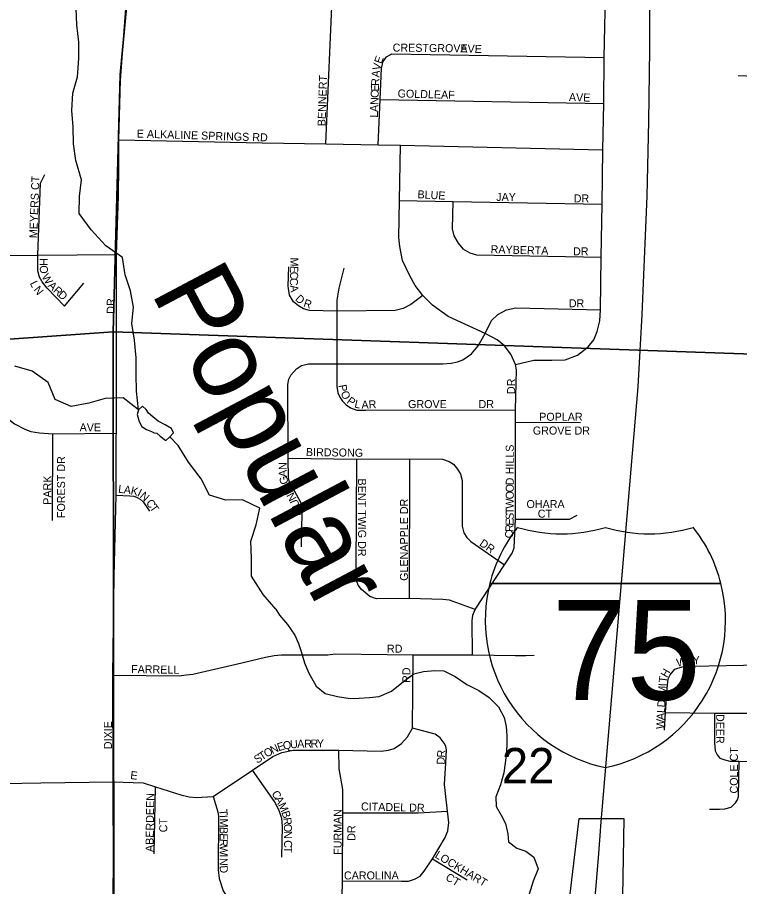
# Model space of a CAD drawing. Extents: x 8.5 to 81.5, y -1.2 to 22.4.
# Drawn here: x 52.1 to 52.954, y 18.242 to 19.27 of the extents above; entities that cross this region are included whole.
import ezdxf

# ---------------------------------------------------------------- set-up
doc = ezdxf.new("R2010")
doc.units = 0
for name, color, linetype in [('GM_X_City_Street', 7, 'Continuous'), ('GM_X_City_Street_Text', 7, 'Continuous'), ('GM_X_Corporation', 7, 'Continuous'), ('GM_X_Interstate_Route', 7, 'Continuous'), ('GM_X_Interstate_Shield', 7, 'Continuous'), ('GM_X_Minor_Lake', 7, 'Continuous'), ('GM_X_Minor_River', 7, 'Continuous'), ('GM_X_Minor_River_Text', 7, 'Continuous'), ('GM_X_Section', 7, 'Continuous'), ('GM_X_Section_Text', 7, 'Continuous')]:
    doc.layers.add(name, color=color, linetype=linetype)

msp = doc.modelspace()

# ---------------------------------------------------------------- linework, layer by layer
at = {"layer": 'GM_X_City_Street'}
for points in [[(52.2203, 19.0942), (52.2204, 19.1255), (52.2222, 19.196), (52.2289, 19.2859), (52.2345, 19.3364), (52.248, 19.4726), (52.2538, 19.5299), (52.2571, 19.5612)], [(52.4651, 19.1207), (52.4735, 19.3103), (52.4794, 19.4085)], [(52.6891, 18.8597), (52.711, 18.8647), (52.7324, 18.8647), (52.7481, 18.8653), (52.7627, 18.8707), (52.7753, 18.8807), (52.7818, 18.8889), (52.7858, 18.8985), (52.789, 18.9113), (52.7899, 18.9244), (52.7905, 18.9867), (52.7919, 19.0492), (52.7927, 19.1136), (52.7937, 19.1683), (52.7942, 19.2229), (52.7953, 19.2774), (52.795, 19.2908), (52.7938, 19.2992), (52.7896, 19.3089), (52.7833, 19.3181), (52.7659, 19.3363), (52.7597, 19.3471), (52.7567, 19.3597), (52.7551, 19.3906)], [(52.5268, 19.1196), (52.5291, 19.1731), (52.5308, 19.2103), (52.5328, 19.2181), (52.5368, 19.2234), (52.5431, 19.2273)], [(52.5431, 19.2273), (52.7942, 19.2229)], [(52.9524, 19.2013), (53.238, 19.1895)], [(52.5291, 19.1731), (52.7937, 19.1683)], [(52.2204, 19.1255), (52.3897, 19.1217), (52.4651, 19.1207), (52.5268, 19.1196), (52.5534, 19.1192), (52.7927, 19.1136)], [(52.6385, 18.5162), (52.6382, 18.5563), (52.639, 18.5631), (52.6416, 18.5697), (52.6764, 18.6228), (52.6854, 18.6366), (52.6876, 18.643), (52.6891, 18.6768), (52.6891, 18.7915), (52.6893, 18.8059), (52.6906, 18.8533), (52.6891, 18.8597), (52.6837, 18.8718), (52.6763, 18.8816), (52.6677, 18.889), (52.6533, 18.8962), (52.6098, 18.9164), (52.5911, 18.9297), (52.5797, 18.9413), (52.5706, 18.9532), (52.5643, 18.9646), (52.5558, 18.9828), (52.5527, 18.9991), (52.5513, 19.0099), (52.5521, 19.0538), (52.5534, 19.1192)], [(52.2173, 18.7751), (52.2174, 18.7786), (52.2176, 18.9899), (52.2201, 19.0589), (52.2203, 19.0942)], [(52.1246, 18.9891), (52.1278, 19.0743), (52.1327, 19.0845)], [(52.5521, 19.0538), (52.6152, 19.0525), (52.7919, 19.0492)], [(52.6152, 19.0525), (52.6144, 19.0201), (52.6164, 19.0118), (52.6215, 19.0031), (52.627, 18.9963), (52.6353, 18.9917), (52.6431, 18.9894), (52.7905, 18.9867)], [(51.7191, 18.9313), (51.9795, 18.9475), (51.9902, 18.9492), (52.047, 18.979), (52.0616, 18.9857), (52.0679, 18.9879), (52.0756, 18.9884), (52.1246, 18.9891), (52.2176, 18.9899)], [(52.1563, 18.9285), (52.1356, 18.9499), (52.1296, 18.9574), (52.1264, 18.9628), (52.1247, 18.9703), (52.1246, 18.9891)], [(52.5797, 18.9413), (52.5654, 18.9307), (52.5563, 18.926), (52.5472, 18.9235), (52.4781, 18.9228), (52.4458, 18.9235), (52.4387, 18.9256), (52.4329, 18.9289), (52.427, 18.9336), (52.4223, 18.9417), (52.4207, 18.9523), (52.4214, 18.9752)], [(52.4863, 18.9735), (52.4804, 18.9499), (52.4781, 18.9356), (52.4781, 18.9228), (52.478, 18.8605), (52.4781, 18.8336), (52.4794, 18.8262), (52.4818, 18.821), (52.4847, 18.8164), (52.4889, 18.8118), (52.4944, 18.8084), (52.5018, 18.8057), (52.5118, 18.8058), (52.6893, 18.8059)], [(52.1563, 18.9285), (52.1789, 18.9557)], [(52.4364, 18.644), (52.437, 18.6847), (52.437, 18.6911), (52.4357, 18.6963), (52.4283, 18.7096), (52.423, 18.7178), (52.4208, 18.7248), (52.4205, 18.7487), (52.42, 18.8359), (52.4213, 18.8425), (52.4235, 18.847), (52.4303, 18.8544), (52.4364, 18.8585), (52.4445, 18.8605), (52.478, 18.8605), (52.6033, 18.8605), (52.6132, 18.8611), (52.6206, 18.8627), (52.6271, 18.8653), (52.6373, 18.8723), (52.6452, 18.8816), (52.6533, 18.8962), (52.661, 18.9116), (52.6685, 18.9189), (52.6787, 18.9244), (52.6896, 18.9265), (52.7899, 18.9244)], [(51.7609, 18.7739), (51.799, 18.7725), (51.8074, 18.773), (51.8146, 18.7746), (51.8486, 18.7875), (51.8997, 18.8069), (51.9083, 18.8096), (51.9153, 18.8107), (52.0531, 18.8123), (52.0634, 18.8118), (52.072, 18.8085), (52.0969, 18.7893), (52.1092, 18.7833), (52.1164, 18.7805), (52.1264, 18.779), (52.1424, 18.7778), (52.2174, 18.7786)], [(52.6891, 18.7915), (52.766, 18.791)], [(52.1418, 18.6753), (52.1424, 18.7778)], [(52.2138, 18.3662), (52.2133, 18.4923), (52.2149, 18.6092), (52.2171, 18.7052), (52.2173, 18.7751)], [(52.4205, 18.7487), (52.5016, 18.7477), (52.5643, 18.748), (52.6028, 18.7477), (52.6109, 18.745), (52.6159, 18.7417), (52.6209, 18.736), (52.6243, 18.7299), (52.6262, 18.7226), (52.6261, 18.6686), (52.6283, 18.6606), (52.6318, 18.6549), (52.6366, 18.6501), (52.6764, 18.6228)], [(52.6416, 18.5697), (52.6114, 18.581), (52.6033, 18.5816), (52.5639, 18.5829), (52.5251, 18.5823), (52.5172, 18.5853), (52.5072, 18.5936), (52.5034, 18.5987), (52.5019, 18.603), (52.5012, 18.6096), (52.5011, 18.6176), (52.5016, 18.7477)], [(52.5639, 18.5829), (52.5643, 18.748)], [(52.2171, 18.7052), (52.2332, 18.7044), (52.2379, 18.7038), (52.2412, 18.7028), (52.2455, 18.7005), (52.2492, 18.6971), (52.2565, 18.6861)], [(52.6891, 18.6768), (52.7533, 18.6769), (52.762, 18.6816)], [(52.8656, 18.427), (52.8665, 18.4479), (52.8686, 18.4769), (52.8697, 18.4878), (52.8721, 18.4926), (52.8777, 18.4992), (52.8865, 18.5021), (52.8975, 18.5028), (53.0204, 18.5053), (53.0789, 18.5046), (53.0959, 18.504), (53.1052, 18.5047), (53.1139, 18.5089), (53.126, 18.5178), (53.1646, 18.5444), (53.1712, 18.5485), (53.1779, 18.5495), (53.2316, 18.5496)], [(52.2133, 18.4923), (52.2918, 18.4916), (52.3, 18.4924), (52.3079, 18.4935), (52.359, 18.5052), (52.3936, 18.5134), (52.4039, 18.5155), (52.4126, 18.5161), (52.4673, 18.5162), (52.4762, 18.5175), (52.5683, 18.5163), (52.6385, 18.5162), (52.689, 18.5154), (52.7013, 18.5155), (52.7114, 18.5157)], [(52.2138, 18.3662), (52.2492, 18.3649), (52.2636, 18.3601), (52.2938, 18.3507), (52.3033, 18.3482), (52.3118, 18.3474), (52.332, 18.3486), (52.3785, 18.3799), (52.4023, 18.3958), (52.4129, 18.4009), (52.4264, 18.4034), (52.4803, 18.4035), (52.5303, 18.4025), (52.539, 18.4033), (52.5457, 18.4054), (52.5544, 18.4112), (52.5616, 18.4192), (52.5675, 18.4296), (52.5683, 18.5163)], [(52.8665, 18.4479), (52.9246, 18.4471), (53.0761, 18.4473)], [(52.9246, 18.4471), (52.9244, 18.4127), (52.9254, 18.4027), (52.9275, 18.398), (52.9309, 18.3942), (52.9368, 18.3921), (52.9425, 18.3904), (52.9537, 18.3903), (53.022, 18.3893), (53.0309, 18.3896), (53.0373, 18.3907), (53.0463, 18.3938), (53.0537, 18.3975), (53.0607, 18.3997), (53.0893, 18.4003)], [(52.4847, 18.2489), (52.5547, 18.2484), (52.5629, 18.2487), (52.5697, 18.2511), (52.5766, 18.2546), (52.5812, 18.2603), (52.5912, 18.275), (52.6061, 18.3001), (52.6093, 18.308), (52.6104, 18.318), (52.6089, 18.3315), (52.6066, 18.3523), (52.6054, 18.363), (52.607, 18.3884), (52.6077, 18.4038), (52.6071, 18.4082), (52.605, 18.4119), (52.6004, 18.418), (52.5943, 18.4223), (52.5675, 18.4296)], [(52.4832, 18.1724), (52.4847, 18.2489), (52.4852, 18.3294), (52.4852, 18.3569), (52.4807, 18.3814), (52.4803, 18.4035)], [(52.9188, 18.3337), (52.9304, 18.3337), (52.9366, 18.334), (52.9444, 18.3362), (52.9495, 18.3413), (52.9517, 18.3448), (52.9529, 18.3486), (52.9537, 18.3903)], [(52.4132, 18.277), (52.414, 18.3134), (52.4129, 18.3226), (52.4098, 18.3321), (52.4042, 18.3426), (52.3785, 18.3799)], [(51.7078, 18.3589), (51.7122, 18.359), (51.8946, 18.3605), (52.0166, 18.3628), (52.0609, 18.3636), (52.1282, 18.3647), (52.2138, 18.3662)], [(52.2123, 18.0013), (52.2118, 18.0943), (52.212, 18.1616), (52.214, 18.2623), (52.2138, 18.3662)], [(52.2622, 18.281), (52.2636, 18.3601)], [(52.332, 18.3486), (52.3373, 18.3307), (52.3382, 18.3251), (52.3376, 18.2621), (52.3388, 18.2515), (52.3438, 18.2372), (52.3494, 18.2285), (52.3558, 18.2206), (52.3616, 18.2159), (52.4379, 18.1824), (52.4513, 18.1763), (52.4635, 18.173), (52.4832, 18.1724), (52.5694, 18.1717), (52.6621, 18.172), (52.6715, 18.1696), (52.6774, 18.1655), (52.6857, 18.1561)], [(52.4852, 18.3294), (52.5743, 18.3292), (52.6089, 18.3315)], [(52.5912, 18.275), (52.632, 18.2503)]]:
    msp.add_lwpolyline(points, dxfattribs=at)
at = {"layer": 'GM_X_Corporation'}
msp.add_lwpolyline([(52.7421, 18.1344), (52.7644, 18.3228), (52.8174, 18.3227), (52.8146, 18.1614)], dxfattribs=at)
at = {"layer": 'GM_X_Interstate_Route'}
for points in [[(52.7898, 18.3076), (52.7903, 18.3139), (52.8344, 18.8332), (52.839, 18.9187), (52.8449, 19.0588), (52.8469, 19.1476), (52.8482, 19.2324), (52.8482, 19.3199), (52.8469, 19.4954), (52.8469, 19.5737), (52.8476, 19.7116), (52.8462, 19.8917), (52.8462, 19.9189), (52.8456, 20.1807), (52.8462, 20.2622), (52.8469, 20.3644), (52.8456, 20.4852), (52.846, 20.5233), (52.8459, 20.8515)], [(52.7548, 17.8881), (52.7556, 17.8973), (52.7613, 17.9651), (52.7626, 17.9775), (52.7635, 17.9886), (52.7656, 18.0162), (52.7663, 18.0252), (52.7683, 18.0482), (52.7793, 18.1944), (52.7842, 18.2384), (52.7876, 18.2811), (52.7898, 18.3076)]]:
    msp.add_lwpolyline(points, dxfattribs=at)
at = {"layer": 'GM_X_Interstate_Shield'}
for p, q in [((52.6589, 18.6005), (52.9322, 18.6005)), ((52.9322, 18.6005), (52.6589, 18.6005)), ((52.9322, 18.6005), (52.6589, 18.6005))]:
    msp.add_line(p, q, dxfattribs=at)
for centre, start, end in [((52.8311, 18.557), 141.669, 165.8066), ((52.7437, 18.8369), 253.0091, 286.9909), ((52.8474, 18.8369), 253.0091, 286.9909), ((52.76, 18.557), 14.1934, 38.331), ((52.8311, 18.557), 165.8066, 258.463), ((52.76, 18.557), 281.537, 14.1934)]:
    msp.add_arc(centre, 0.1776, start, end, dxfattribs=at)
at = {"layer": 'GM_X_Minor_Lake'}
for points in [[(52.2808, 18.7739), (52.2851, 18.7788), (52.2825, 18.7838), (52.275, 18.7881), (52.2667, 18.7928), (52.2607, 18.7978), (52.2554, 18.8021), (52.2525, 18.8063), (52.2484, 18.8102), (52.2434, 18.8061), (52.2421, 18.8004), (52.2443, 18.7924), (52.2476, 18.7863), (52.2532, 18.7827), (52.2589, 18.7804), (52.2623, 18.7788)], [(52.2623, 18.7788), (52.2653, 18.7784), (52.2691, 18.7749), (52.2758, 18.7698), (52.2808, 18.7739)]]:
    msp.add_lwpolyline(points, dxfattribs=at)
at = {"layer": 'GM_X_Minor_River'}
for points in [[(52.2434, 18.8061), (52.2413, 18.8283), (52.2409, 18.848), (52.2409, 18.8674), (52.239, 18.8883), (52.2359, 18.9081), (52.2375, 18.9274), (52.234, 18.9468), (52.228, 18.9658), (52.2245, 18.9863), (52.2051, 19), (52.1876, 19.019), (52.1736, 19.0384), (52.1739, 19.0585), (52.1762, 19.0782), (52.1694, 19.101), (52.1667, 19.1208), (52.1663, 19.1409), (52.1648, 19.1599), (52.1659, 19.1804), (52.1713, 19.1998), (52.1732, 19.2215), (52.1732, 19.2408), (52.1705, 19.2613), (52.1701, 19.2807)], [(52.2434, 18.8061), (52.2253, 18.8203), (52.204, 18.8196), (52.185, 18.8139), (52.1641, 18.8101), (52.1451, 18.8184), (52.1367, 18.8382), (52.1177, 18.8519), (52.0975, 18.8576)], [(52.4058, 18.5703), (52.3911, 18.5878), (52.3771, 18.6092), (52.3771, 18.6307), (52.3763, 18.6505), (52.3828, 18.6702), (52.3869, 18.6896), (52.3664, 18.6995), (52.347, 18.6991), (52.3276, 18.7052), (52.3177, 18.7246), (52.3029, 18.7443), (52.2903, 18.7637), (52.2808, 18.7739)], [(52.4058, 18.5703), (52.4101, 18.5632), (52.4198, 18.552), (52.4283, 18.5397), (52.4326, 18.5297), (52.4359, 18.5201), (52.4398, 18.5067), (52.4445, 18.4953), (52.4537, 18.4791), (52.4641, 18.4705), (52.4789, 18.4668), (52.494, 18.4646), (52.5043, 18.4651), (52.5168, 18.4656), (52.5283, 18.4669), (52.5428, 18.4731), (52.5567, 18.4846), (52.5691, 18.4938), (52.5805, 18.4966), (52.5938, 18.4978), (52.6045, 18.4972), (52.618, 18.4905), (52.6319, 18.4811), (52.6458, 18.474), (52.6582, 18.4657), (52.669, 18.4549), (52.6759, 18.4422), (52.6784, 18.4315), (52.6789, 18.4208), (52.6791, 18.4113), (52.6786, 18.4015), (52.6772, 18.3882), (52.6754, 18.3765), (52.6717, 18.3625), (52.6661, 18.3482), (52.6666, 18.3368), (52.6725, 18.3268), (52.6773, 18.3168), (52.6804, 18.3046), (52.681, 18.295), (52.6908, 18.2876), (52.7013, 18.284), (52.7111, 18.2769), (52.7161, 18.2632), (52.7101, 18.2485), (52.7053, 18.233)]]:
    msp.add_lwpolyline(points, dxfattribs=at)
at = {"layer": 'GM_X_Section'}
for points in [[(52.284, 19.8673), (52.2219, 19.2023), (52.2136, 18.8983), (51.6895, 18.8611), (51.2202, 18.8578), (51.2184, 19.3702), (51.2391, 19.8686)], [(52.284, 19.8673), (53.2345, 19.8635), (53.2294, 18.8627), (52.2136, 18.8983), (52.2219, 19.2023)], [(52.2136, 18.8983), (52.2149, 17.8371), (51.2117, 17.8427), (51.2202, 18.8578), (51.6895, 18.8611)], [(52.2136, 18.8983), (53.2294, 18.8627), (53.2272, 17.8352), (52.2149, 17.8371)]]:
    msp.add_lwpolyline(points, close=True, dxfattribs=at)

# ---------------------------------------------------------------- texts
at = {"layer": 'GM_X_City_Street_Text'}
for s, rotation, p in [('CRESTGROVE', 359.3707, (52.544, 19.2298)), ('AVE', 358.0261, (52.624, 19.2289)), ('V', 77.5504, (52.5291, 19.2068)), ('E', 70.7788, (52.5309, 19.2147)), ('A', 84.322, (52.5284, 19.1988)), ('BENNERT', 88.2076, (52.4647, 19.1414)), ('R', 87.7077, (52.528, 19.189)), ('E', 87.7077, (52.5277, 19.1823)), ('GOLDLEAF', 358.4285, (52.5498, 19.1756)), ('N', 87.7077, (52.5271, 19.1665)), ('C', 87.7077, (52.5274, 19.1748)), ('AVE', 358.0261, (52.7523, 19.1714)), ('A', 87.7077, (52.5267, 19.1582)), ('L', 87.7077, (52.5265, 19.1515)), ('E ALKALINE SPRINGS RD', 358.2757, (52.2415, 19.1281)), ('MEYERS CT', 87.7986, (52.1238, 19.0089)), ('BLUE', 356.8219, (52.5732, 19.0564)), ('JAY', 0, (52.6665, 19.0531)), ('DR', 0, (52.7581, 19.0514)), ('RAYBERTA', 358.4704, (52.6598, 18.9913)), ('DR', 0, (52.7573, 18.9888)), ('H', 270.5028, (52.1266, 18.9855)), ('M', 268.8524, (52.4232, 18.9863)), ('O', 273.6255, (52.1267, 18.9766)), ('E', 268.8253, (52.423, 18.9763)), ('L', 295.38, (52.1149, 18.9559)), ('W', 301.4569, (52.1287, 18.9635)), ('C', 268.8343, (52.4227, 18.9621)), ('C', 268.8656, (52.4229, 18.9696)), ('N', 308.4955, (52.119, 18.9479)), ('A', 315.1424, (52.1359, 18.9523)), ('R', 317.188, (52.142, 18.9462)), ('A', 277.04, (52.4227, 18.9531)), ('D', 317.3899, (52.1476, 18.9411)), ('D', 316.9918, (52.4281, 18.9364)), ('DR', 90, (52.2155, 18.9197)), ('R', 341.5004, (52.4379, 18.9284)), ('DR', 0, (52.7523, 18.9273)), ('P', 280.9939, (52.4799, 18.835)), ('DR', 90, (52.6888, 18.8247)), ('O', 296.585, (52.4821, 18.8258)), ('P', 324.1901, (52.489, 18.8146)), ('L', 347.3874, (52.4983, 18.809)), ('A', 1.6379, (52.5073, 18.8073)), ('R', 3.0217, (52.5159, 18.8076)), ('GROVE', 0, (52.5623, 18.8081)), ('DR', 0, (52.6456, 18.8081)), ('POPLAR', 0, (52.7173, 18.7931)), ('AVE', 0, (52.174, 18.7806)), ('GROVE DR', 0, (52.7098, 18.7768)), ('HILLS', 90, (52.6872, 18.7297)), ('BIRDSONG', 359.1935, (52.4415, 18.7514)), ('FOREST DR', 90, (52.1568, 18.678)), ('N', 90, (52.4188, 18.7349)), ('A', 91.1803, (52.419, 18.7267)), ('PARK', 90, (52.1405, 18.6938)), ('G', 106.8521, (52.4213, 18.7194)), ('BENT TWIG DR', 270, (52.5032, 18.7247)), ('D', 89.9928, (52.6872, 18.7167)), ('L', 353.2072, (52.2192, 18.7081)), ('A', 352.8994, (52.2258, 18.7073)), ('K', 346.9497, (52.2338, 18.7063)), ('I', 333.9238, (52.2414, 18.7046)), ('I', 115.6268, (52.423, 18.716)), ('N', 117.1223, (52.4267, 18.7086)), ('O', 89.9928, (52.6872, 18.7084)), ('N', 318.0615, (52.2445, 18.7032)), ('N', 119.0106, (52.4308, 18.7014)), ('O', 89.9928, (52.6872, 18.7001)), ('C', 305.981, (52.2519, 18.696)), ('T', 305.5313, (52.2563, 18.69)), ('U', 113.6848, (52.4345, 18.6929)), ('GLENAPPLE DR', 90, (52.5622, 18.6038)), ('W', 89.9988, (52.6872, 18.6892)), ('OHARA', 0, (52.7023, 18.6898)), ('D', 90.6995, (52.4355, 18.6805)), ('S', 89.3044, (52.6871, 18.6758)), ('T', 89.9707, (52.6872, 18.6826)), ('CT', 0, (52.7156, 18.6785)), ('E', 88.1599, (52.6869, 18.6689)), ('C', 87.984, (52.6863, 18.6539)), ('R', 87.984, (52.6866, 18.6614)), ('DR', 325.5013, (52.6458, 18.6461)), ('RD', 0, (52.5373, 18.5188)), ('W', 11.2539, (52.8806, 18.5021)), ('A', 4.9234, (52.8909, 18.5042)), ('Y', 4.2445, (52.8992, 18.5049)), ('FARRELL', 359.0765, (52.2348, 18.4947)), ('RD', 90, (52.565, 18.483)), ('H', 60.3148, (52.8684, 18.4885)), ('T', 82.9868, (52.8679, 18.4828)), ('M', 86.5736, (52.8671, 18.4688)), ('I', 86.5984, (52.8677, 18.4788)), ('S', 86.5822, (52.8667, 18.4622)), ('D', 86.5886, (52.8662, 18.4539)), ('A', 86.5668, (52.8653, 18.4389)), ('L', 86.595, (52.8658, 18.4472)), ('DEER', 270, (52.9266, 18.4463)), ('DIXIE', 90, (52.2122, 18.4047)), ('W', 86.5852, (52.8647, 18.4281)), ('Q', 10.4182, (52.4152, 18.404)), ('U', 5.3626, (52.4232, 18.4055)), ('A', 1.1584, (52.4313, 18.4062)), ('R', 0.9714, (52.4396, 18.4064)), ('R', 0.9472, (52.4471, 18.4065)), ('Y', 0.9728, (52.4546, 18.4067)), ('O', 30.4877, (52.395, 18.3945)), ('N', 25.079, (52.4019, 18.3987)), ('E', 17.5708, (52.4092, 18.4021)), ('COLE CT', 90, (52.9522, 18.3522)), ('S', 32.9322, (52.3839, 18.3873)), ('T', 32.9027, (52.3895, 18.391)), ('D', 87.4858, (52.6055, 18.3862)), ('R', 86.8417, (52.6059, 18.3945)), ('E', 352.8783, (52.2335, 18.3695)), ('C', 300.6847, (52.4005, 18.3523)), ('ABERDEEN', 89.2262, (52.2613, 18.283)), ('A', 299.2732, (52.4043, 18.3459)), ('M', 295.237, (52.4083, 18.3388)), ('CITADEL DR', 358.5864, (52.5065, 18.3323)), ('T', 275.0609, (52.339, 18.3333)), ('B', 288.2276, (52.4124, 18.33)), ('FURMAN', 90, (52.4838, 18.2797)), ('CT', 90, (52.2776, 18.3063)), ('I', 272.6244, (52.3396, 18.3267)), ('M', 269.6175, (52.3398, 18.3227)), ('R', 276.1069, (52.4146, 18.3234)), ('B', 269.5385, (52.3397, 18.3127)), ('O', 271.8363, (52.4154, 18.3161)), ('DR', 90, (52.5, 18.2963)), ('E', 269.5355, (52.3397, 18.3052)), ('N', 270.2186, (52.4157, 18.3079)), ('W', 269.5364, (52.3396, 18.291)), ('R', 269.5241, (52.3396, 18.2985)), ('C', 269.994, (52.4157, 18.297)), ('T', 269.9956, (52.4157, 18.2895)), ('LOCKHART', 329.0387, (52.5932, 18.277)), ('N', 269.5359, (52.3395, 18.276)), ('I', 269.5193, (52.3395, 18.2802)), ('D', 274.6153, (52.3394, 18.2668)), ('CAROLINA', 0, (52.4865, 18.2506)), ('CT', 329.0384, (52.6057, 18.2506))]:
    msp.add_text(s, height=0.00947, rotation=rotation, dxfattribs=at).set_placement(p)
at = {"layer": 'GM_X_Interstate_Shield'}
msp.add_text('75', height=0.11837, dxfattribs=at).set_placement((52.7323, 18.4629))
at = {"layer": 'GM_X_Minor_River_Text'}
msp.add_text('Popular', height=0.09469, rotation=297.917, dxfattribs=at).set_placement((52.2574, 18.9456))
at = {"layer": 'GM_X_Section_Text'}
msp.add_text('22', height=0.04186, rotation=0, dxfattribs=at).set_placement((52.6731, 18.3642))

doc.saveas('drawing.dxf')
